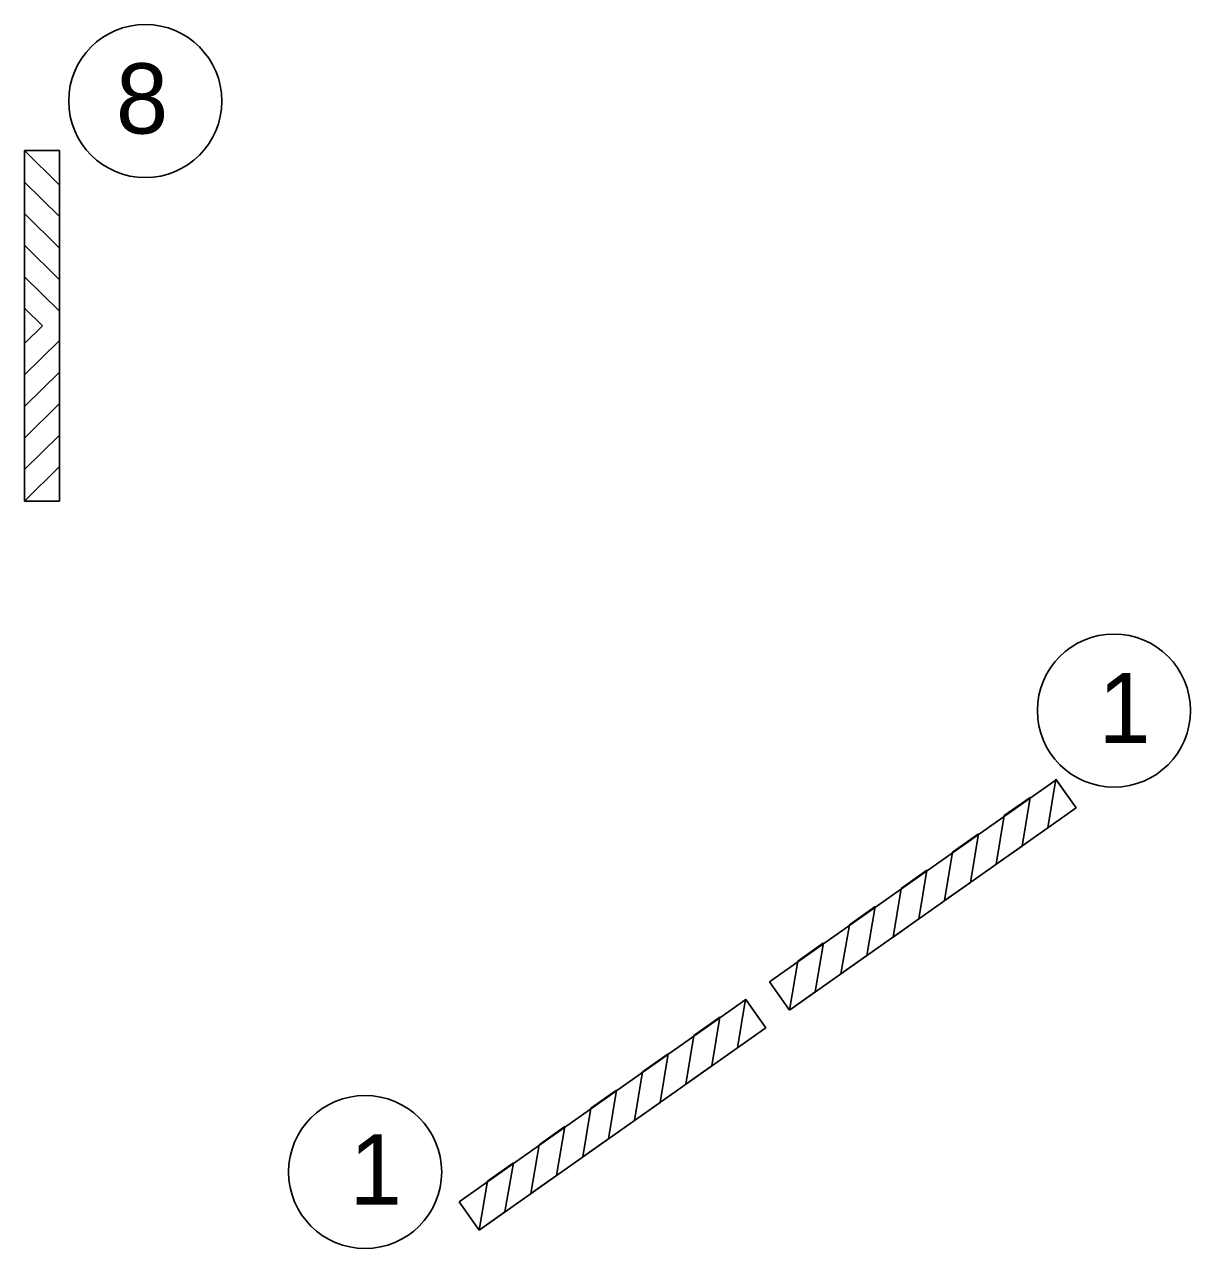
# Model space of a CAD drawing. Extents: x 1615234 to 1620694, y 898143 to 902846.
# Drawn here: x 1616786.8 to 1617145.5, y 898142.6 to 898519.3 of the extents above; entities that cross this region are included whole.
import ezdxf

# ---------------------------------------------------------------- set-up
doc = ezdxf.new("R2010")
doc.units = 0
doc.layers.add('DEV TYPE 3 BARRICADE CELL', color=7, linetype='Continuous')
doc.layers.add('Old_Level_28', color=7, linetype='Continuous')

msp = doc.modelspace()

# ---------------------------------------------------------------- linework, layer by layer
at = {"layer": 'DEV TYPE 3 BARRICADE CELL'}
for p, q in [((1616786.78, 898480.51), (1616797.59, 898480.51)), ((1616797.59, 898469.89), (1616786.78, 898480.51)), ((1616786.78, 898372.59), (1616786.78, 898480.51)), ((1616786.78, 898480.51), (1616797.59, 898480.51)), ((1616797.59, 898480.51), (1616797.59, 898469.89)), ((1616797.59, 898480.51), (1616797.59, 898372.59)), ((1616786.78, 898470.8), (1616797.59, 898460.17)), ((1616786.78, 898461.09), (1616786.78, 898470.8)), ((1616797.59, 898450.46), (1616786.78, 898461.09)), ((1616797.59, 898460.17), (1616797.59, 898450.46)), ((1616786.78, 898451.38), (1616797.59, 898440.75)), ((1616786.78, 898441.67), (1616786.78, 898451.38)), ((1616797.59, 898431.04), (1616786.78, 898441.67)), ((1616797.59, 898440.75), (1616797.59, 898431.04)), ((1616786.78, 898431.96), (1616792.28, 898426.55)), ((1616786.78, 898422.25), (1616786.78, 898431.96)), ((1616786.78, 898430.86), (1616786.78, 898421.15)), ((1616792.28, 898426.55), (1616786.78, 898421.15)), ((1616797.59, 898422.06), (1616786.78, 898411.43)), ((1616797.59, 898412.35), (1616797.59, 898422.06)), ((1616786.78, 898401.72), (1616797.59, 898412.35)), ((1616786.78, 898411.43), (1616786.78, 898401.72)), ((1616797.59, 898402.64), (1616786.78, 898392.01)), ((1616797.59, 898392.93), (1616797.59, 898402.64)), ((1616786.78, 898382.3), (1616797.59, 898392.93)), ((1616786.78, 898392.01), (1616786.78, 898382.3)), ((1616797.59, 898383.22), (1616786.78, 898372.59)), ((1616797.59, 898372.59), (1616797.59, 898383.22)), ((1616797.59, 898372.59), (1616786.78, 898372.59)), ((1616786.78, 898372.59), (1616797.59, 898372.59)), ((1617015.96, 898224.65), (1617104.15, 898286.88)), ((1617101.6, 898272.07), (1617104.05, 898287.03)), ((1617104.05, 898287.03), (1617110.28, 898278.19)), ((1617104.15, 898286.88), (1617110.28, 898278.19)), ((1617088.18, 898275.83), (1617096.11, 898281.43)), ((1617096.11, 898281.43), (1617093.66, 898266.47)), ((1617110.28, 898278.19), (1617022.08, 898215.97)), ((1617085.72, 898260.87), (1617088.18, 898275.83)), ((1617110.28, 898278.19), (1617101.6, 898272.07)), ((1617072.3, 898264.63), (1617080.24, 898270.23)), ((1617080.24, 898270.23), (1617077.79, 898255.27)), ((1617069.85, 898249.67), (1617072.3, 898264.63)), ((1617093.66, 898266.47), (1617085.72, 898260.87)), ((1617056.43, 898253.43), (1617064.37, 898259.03)), ((1617064.37, 898259.03), (1617061.91, 898244.07)), ((1617053.98, 898238.47), (1617056.43, 898253.43)), ((1617077.79, 898255.27), (1617069.85, 898249.67)), ((1617040.56, 898242.23), (1617048.49, 898247.83)), ((1617048.49, 898247.83), (1617045.89, 898232.77)), ((1617037.96, 898227.17), (1617040.56, 898242.23)), ((1617061.91, 898244.07), (1617053.98, 898238.47)), ((1617024.68, 898231.04), (1617032.62, 898236.64)), ((1617032.62, 898236.64), (1617030.02, 898221.57)), ((1617022.08, 898215.97), (1617024.68, 898231.04)), ((1617045.89, 898232.77), (1617037.96, 898227.17)), ((1617022.08, 898215.97), (1617015.96, 898224.65)), ((1616920.5, 898156.99), (1617008.7, 898219.21)), ((1617006.14, 898204.4), (1617008.6, 898219.36)), ((1617008.6, 898219.36), (1617014.83, 898210.53)), ((1617008.7, 898219.21), (1617014.83, 898210.53)), ((1617030.02, 898221.57), (1617022.08, 898215.97)), ((1617014.83, 898210.53), (1616926.63, 898148.3)), ((1616992.72, 898208.17), (1617000.66, 898213.76)), ((1617000.66, 898213.76), (1616998.21, 898198.8)), ((1617014.83, 898210.53), (1617006.14, 898204.4)), ((1616990.27, 898193.2), (1616992.72, 898208.17)), ((1616976.85, 898196.97), (1616984.79, 898202.57)), ((1616984.79, 898202.57), (1616982.33, 898187.6)), ((1616974.4, 898182), (1616976.85, 898196.97)), ((1616998.21, 898198.8), (1616990.27, 898193.2)), ((1616960.98, 898185.77), (1616968.91, 898191.37)), ((1616968.91, 898191.37), (1616966.46, 898176.4)), ((1616958.52, 898170.81), (1616960.98, 898185.77)), ((1616982.33, 898187.6), (1616974.4, 898182)), ((1616945.1, 898174.57), (1616953.04, 898180.17)), ((1616953.04, 898180.17), (1616950.44, 898165.1)), ((1616942.5, 898159.5), (1616945.1, 898174.57)), ((1616966.46, 898176.4), (1616958.52, 898170.81)), ((1616929.23, 898163.37), (1616937.17, 898168.97)), ((1616937.17, 898168.97), (1616934.57, 898153.9)), ((1616926.63, 898148.3), (1616929.23, 898163.37)), ((1616950.44, 898165.1), (1616942.5, 898159.5)), ((1616926.63, 898148.3), (1616920.5, 898156.99)), ((1616934.57, 898153.9), (1616926.63, 898148.3))]:
    msp.add_line(p, q, dxfattribs=at)
at = {"layer": 'Old_Level_28'}
for centre in [(1616823.93, 898495.74), (1617121.93, 898308.16), (1616891.57, 898166.17)]:
    msp.add_circle(centre, 23.55, dxfattribs=at)

# ---------------------------------------------------------------- texts
for s, p in [('8', (1616814.91, 898485.73)), ('1', (1617117.16, 898298.15)), ('1', (1616886.8, 898156.15))]:
    msp.add_text(s, height=21.6, dxfattribs=at).set_placement(p)

doc.saveas('drawing.dxf')
